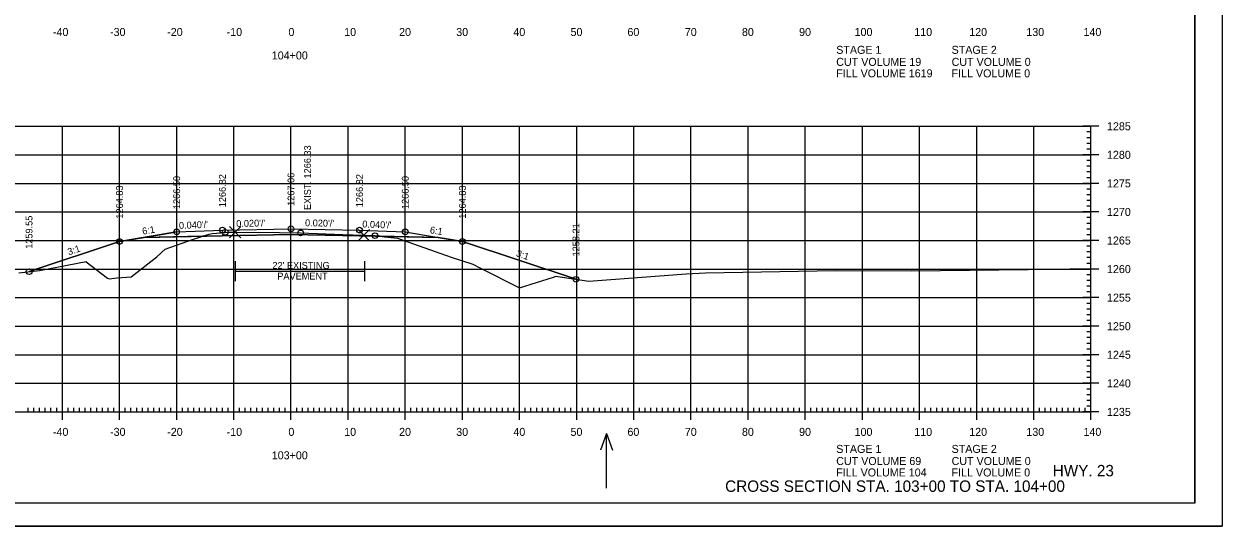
# Model space of a CAD drawing. Extents: x 1406028 to 1412453, y 321733 to 325986.
# Drawn here: x 1406543.2 to 1406752.8, y 322146 to 322233.9 of the extents above; entities that cross this region are included whole.
import ezdxf

# ---------------------------------------------------------------- set-up
doc = ezdxf.new("R2010")
doc.units = 0
for name, color, linetype in [('R_Alt Surface', 7, 'Continuous'), ('R_Axis', 7, 'Continuous'), ('R_Axis Annot', 7, 'Continuous'), ('R_Border', 7, 'Continuous'), ('R_Draft', 7, 'Continuous'), ('R_Exist Surface', 7, 'Continuous'), ('R_Fin Surface', 7, 'Continuous'), ('R_Fin Surface Annot', 7, 'Continuous'), ('R_Grid', 7, 'Continuous'), ('R_No Plot', 7, 'Continuous'), ('R_Proposed Const Limits', 7, 'Continuous'), ('R_Proposed Road', 7, 'Continuous'), ('R_Water Annot', 7, 'Continuous'), ('R_Xsect Elev', 7, 'Continuous')]:
    doc.layers.add(name, color=color, linetype=linetype)

msp = doc.modelspace()

# ---------------------------------------------------------------- linework, layer by layer
at = {"layer": 'R_Alt Surface'}
msp.add_lwpolyline([(1406564.16, 322196.54), (1406577.88, 322196.81), (1406589.88, 322197.05), (1406601.88, 322196.81), (1406615.61, 322196.54)], dxfattribs=at)
at = {"layer": 'R_Axis'}
for p, q in [((1406731.28, 322215.99), (1406728.48, 322215.99)), ((1406729.88, 322214.99), (1406729.18, 322214.99)), ((1406729.88, 322165.99), (1406729.88, 322215.99)), ((1406729.88, 322213.99), (1406729.18, 322213.99)), ((1406729.88, 322212.99), (1406729.18, 322212.99)), ((1406731.28, 322210.99), (1406728.48, 322210.99)), ((1406729.88, 322211.99), (1406729.18, 322211.99)), ((1406729.88, 322209.99), (1406729.18, 322209.99)), ((1406729.88, 322208.99), (1406729.18, 322208.99)), ((1406729.88, 322207.99), (1406729.18, 322207.99)), ((1406729.88, 322206.99), (1406729.18, 322206.99)), ((1406731.28, 322205.99), (1406728.48, 322205.99)), ((1406729.88, 322204.99), (1406729.18, 322204.99)), ((1406729.88, 322203.99), (1406729.18, 322203.99)), ((1406729.88, 322202.99), (1406729.18, 322202.99)), ((1406731.28, 322200.99), (1406728.48, 322200.99)), ((1406729.88, 322201.99), (1406729.18, 322201.99)), ((1406729.88, 322199.99), (1406729.18, 322199.99)), ((1406729.88, 322198.99), (1406729.18, 322198.99)), ((1406729.88, 322197.99), (1406729.18, 322197.99)), ((1406731.28, 322195.99), (1406728.48, 322195.99)), ((1406729.88, 322196.99), (1406729.18, 322196.99)), ((1406729.88, 322194.99), (1406729.18, 322194.99)), ((1406729.88, 322193.99), (1406729.18, 322193.99)), ((1406729.88, 322192.99), (1406729.18, 322192.99)), ((1406729.88, 322191.99), (1406729.18, 322191.99)), ((1406731.28, 322190.99), (1406728.48, 322190.99)), ((1406729.88, 322189.99), (1406729.18, 322189.99)), ((1406729.88, 322188.99), (1406729.18, 322188.99)), ((1406729.88, 322187.99), (1406729.18, 322187.99)), ((1406731.28, 322185.99), (1406728.48, 322185.99)), ((1406729.88, 322186.99), (1406729.18, 322186.99)), ((1406729.88, 322184.99), (1406729.18, 322184.99)), ((1406729.88, 322183.99), (1406729.18, 322183.99)), ((1406729.88, 322182.99), (1406729.18, 322182.99)), ((1406729.88, 322181.99), (1406729.18, 322181.99)), ((1406731.28, 322180.99), (1406728.48, 322180.99)), ((1406729.88, 322179.99), (1406729.18, 322179.99)), ((1406729.88, 322178.99), (1406729.18, 322178.99)), ((1406729.88, 322177.99), (1406729.18, 322177.99)), ((1406729.88, 322176.99), (1406729.18, 322176.99)), ((1406731.28, 322175.99), (1406728.48, 322175.99)), ((1406729.88, 322174.99), (1406729.18, 322174.99)), ((1406729.88, 322173.99), (1406729.18, 322173.99)), ((1406729.88, 322172.99), (1406729.18, 322172.99)), ((1406731.28, 322170.99), (1406728.48, 322170.99)), ((1406729.88, 322171.99), (1406729.18, 322171.99)), ((1406729.88, 322169.99), (1406729.18, 322169.99)), ((1406729.88, 322168.99), (1406729.18, 322168.99)), ((1406543.88, 322165.99), (1406543.88, 322166.69)), ((1406544.88, 322165.99), (1406544.88, 322166.69)), ((1406545.88, 322165.99), (1406545.88, 322166.69)), ((1406546.88, 322165.99), (1406546.88, 322166.69)), ((1406547.88, 322165.99), (1406547.88, 322166.69)), ((1406548.88, 322165.99), (1406548.88, 322166.69)), ((1406549.88, 322164.59), (1406549.88, 322167.39)), ((1406550.88, 322165.99), (1406550.88, 322166.69)), ((1406551.88, 322165.99), (1406551.88, 322166.69)), ((1406552.88, 322165.99), (1406552.88, 322166.69)), ((1406553.88, 322165.99), (1406553.88, 322166.69)), ((1406554.88, 322165.99), (1406554.88, 322166.69)), ((1406555.88, 322165.99), (1406555.88, 322166.69)), ((1406556.88, 322165.99), (1406556.88, 322166.69)), ((1406557.88, 322165.99), (1406557.88, 322166.69)), ((1406558.88, 322165.99), (1406558.88, 322166.69)), ((1406559.88, 322164.59), (1406559.88, 322167.39)), ((1406560.88, 322165.99), (1406560.88, 322166.69)), ((1406561.88, 322165.99), (1406561.88, 322166.69)), ((1406562.88, 322165.99), (1406562.88, 322166.69)), ((1406563.88, 322165.99), (1406563.88, 322166.69)), ((1406564.88, 322165.99), (1406564.88, 322166.69)), ((1406565.88, 322165.99), (1406565.88, 322166.69)), ((1406566.88, 322165.99), (1406566.88, 322166.69)), ((1406567.88, 322165.99), (1406567.88, 322166.69)), ((1406568.88, 322165.99), (1406568.88, 322166.69)), ((1406569.88, 322164.59), (1406569.88, 322167.39)), ((1406570.88, 322165.99), (1406570.88, 322166.69)), ((1406571.88, 322165.99), (1406571.88, 322166.69)), ((1406572.88, 322165.99), (1406572.88, 322166.69)), ((1406573.88, 322165.99), (1406573.88, 322166.69)), ((1406574.88, 322165.99), (1406574.88, 322166.69)), ((1406575.88, 322165.99), (1406575.88, 322166.69)), ((1406576.88, 322165.99), (1406576.88, 322166.69)), ((1406577.88, 322165.99), (1406577.88, 322166.69)), ((1406578.88, 322165.99), (1406578.88, 322166.69)), ((1406579.88, 322164.59), (1406579.88, 322167.39)), ((1406580.88, 322165.99), (1406580.88, 322166.69)), ((1406581.88, 322165.99), (1406581.88, 322166.69)), ((1406582.88, 322165.99), (1406582.88, 322166.69)), ((1406583.88, 322165.99), (1406583.88, 322166.69)), ((1406584.88, 322165.99), (1406584.88, 322166.69)), ((1406585.88, 322165.99), (1406585.88, 322166.69)), ((1406586.88, 322165.99), (1406586.88, 322166.69)), ((1406587.88, 322165.99), (1406587.88, 322166.69)), ((1406588.88, 322165.99), (1406588.88, 322166.69)), ((1406589.88, 322164.59), (1406589.88, 322167.39)), ((1406590.88, 322165.99), (1406590.88, 322166.69)), ((1406591.88, 322165.99), (1406591.88, 322166.69)), ((1406592.88, 322165.99), (1406592.88, 322166.69)), ((1406593.88, 322165.99), (1406593.88, 322166.69)), ((1406594.88, 322165.99), (1406594.88, 322166.69)), ((1406595.88, 322165.99), (1406595.88, 322166.69)), ((1406596.88, 322165.99), (1406596.88, 322166.69)), ((1406597.88, 322165.99), (1406597.88, 322166.69)), ((1406598.88, 322165.99), (1406598.88, 322166.69)), ((1406599.88, 322164.59), (1406599.88, 322167.39)), ((1406600.88, 322165.99), (1406600.88, 322166.69)), ((1406601.88, 322165.99), (1406601.88, 322166.69)), ((1406602.88, 322165.99), (1406602.88, 322166.69)), ((1406603.88, 322165.99), (1406603.88, 322166.69)), ((1406604.88, 322165.99), (1406604.88, 322166.69)), ((1406605.88, 322165.99), (1406605.88, 322166.69)), ((1406606.88, 322165.99), (1406606.88, 322166.69)), ((1406607.88, 322165.99), (1406607.88, 322166.69)), ((1406608.88, 322165.99), (1406608.88, 322166.69)), ((1406609.88, 322164.59), (1406609.88, 322167.39)), ((1406610.88, 322165.99), (1406610.88, 322166.69)), ((1406611.88, 322165.99), (1406611.88, 322166.69)), ((1406612.88, 322165.99), (1406612.88, 322166.69)), ((1406613.88, 322165.99), (1406613.88, 322166.69)), ((1406614.88, 322165.99), (1406614.88, 322166.69)), ((1406615.88, 322165.99), (1406615.88, 322166.69)), ((1406616.88, 322165.99), (1406616.88, 322166.69)), ((1406617.88, 322165.99), (1406617.88, 322166.69)), ((1406618.88, 322165.99), (1406618.88, 322166.69)), ((1406619.88, 322164.59), (1406619.88, 322167.39)), ((1406620.88, 322165.99), (1406620.88, 322166.69)), ((1406621.88, 322165.99), (1406621.88, 322166.69)), ((1406622.88, 322165.99), (1406622.88, 322166.69)), ((1406623.88, 322165.99), (1406623.88, 322166.69)), ((1406624.88, 322165.99), (1406624.88, 322166.69)), ((1406625.88, 322165.99), (1406625.88, 322166.69)), ((1406626.88, 322165.99), (1406626.88, 322166.69)), ((1406627.88, 322165.99), (1406627.88, 322166.69)), ((1406628.88, 322165.99), (1406628.88, 322166.69)), ((1406629.88, 322164.59), (1406629.88, 322167.39)), ((1406630.88, 322165.99), (1406630.88, 322166.69)), ((1406631.88, 322165.99), (1406631.88, 322166.69)), ((1406632.88, 322165.99), (1406632.88, 322166.69)), ((1406633.88, 322165.99), (1406633.88, 322166.69)), ((1406634.88, 322165.99), (1406634.88, 322166.69)), ((1406635.88, 322165.99), (1406635.88, 322166.69)), ((1406636.88, 322165.99), (1406636.88, 322166.69)), ((1406637.88, 322165.99), (1406637.88, 322166.69)), ((1406638.88, 322165.99), (1406638.88, 322166.69)), ((1406639.88, 322164.59), (1406639.88, 322167.39)), ((1406640.88, 322165.99), (1406640.88, 322166.69)), ((1406641.88, 322165.99), (1406641.88, 322166.69)), ((1406642.88, 322165.99), (1406642.88, 322166.69)), ((1406643.88, 322165.99), (1406643.88, 322166.69)), ((1406644.88, 322165.99), (1406644.88, 322166.69)), ((1406645.88, 322165.99), (1406645.88, 322166.69)), ((1406646.88, 322165.99), (1406646.88, 322166.69)), ((1406647.88, 322165.99), (1406647.88, 322166.69)), ((1406648.88, 322165.99), (1406648.88, 322166.69)), ((1406649.88, 322164.59), (1406649.88, 322167.39)), ((1406650.88, 322165.99), (1406650.88, 322166.69)), ((1406651.88, 322165.99), (1406651.88, 322166.69)), ((1406652.88, 322165.99), (1406652.88, 322166.69)), ((1406653.88, 322165.99), (1406653.88, 322166.69)), ((1406654.88, 322165.99), (1406654.88, 322166.69)), ((1406655.88, 322165.99), (1406655.88, 322166.69)), ((1406656.88, 322165.99), (1406656.88, 322166.69)), ((1406657.88, 322165.99), (1406657.88, 322166.69)), ((1406658.88, 322165.99), (1406658.88, 322166.69)), ((1406659.88, 322164.59), (1406659.88, 322167.39)), ((1406660.88, 322165.99), (1406660.88, 322166.69)), ((1406661.88, 322165.99), (1406661.88, 322166.69)), ((1406662.88, 322165.99), (1406662.88, 322166.69)), ((1406663.88, 322165.99), (1406663.88, 322166.69)), ((1406664.88, 322165.99), (1406664.88, 322166.69)), ((1406665.88, 322165.99), (1406665.88, 322166.69)), ((1406666.88, 322165.99), (1406666.88, 322166.69)), ((1406667.88, 322165.99), (1406667.88, 322166.69)), ((1406668.88, 322165.99), (1406668.88, 322166.69)), ((1406669.88, 322164.59), (1406669.88, 322167.39)), ((1406670.88, 322165.99), (1406670.88, 322166.69)), ((1406671.88, 322165.99), (1406671.88, 322166.69)), ((1406672.88, 322165.99), (1406672.88, 322166.69)), ((1406673.88, 322165.99), (1406673.88, 322166.69)), ((1406674.88, 322165.99), (1406674.88, 322166.69)), ((1406675.88, 322165.99), (1406675.88, 322166.69)), ((1406676.88, 322165.99), (1406676.88, 322166.69)), ((1406677.88, 322165.99), (1406677.88, 322166.69)), ((1406678.88, 322165.99), (1406678.88, 322166.69)), ((1406679.88, 322164.59), (1406679.88, 322167.39)), ((1406680.88, 322165.99), (1406680.88, 322166.69)), ((1406681.88, 322165.99), (1406681.88, 322166.69)), ((1406682.88, 322165.99), (1406682.88, 322166.69)), ((1406683.88, 322165.99), (1406683.88, 322166.69)), ((1406684.88, 322165.99), (1406684.88, 322166.69)), ((1406685.88, 322165.99), (1406685.88, 322166.69)), ((1406686.88, 322165.99), (1406686.88, 322166.69)), ((1406687.88, 322165.99), (1406687.88, 322166.69)), ((1406688.88, 322165.99), (1406688.88, 322166.69)), ((1406689.88, 322164.59), (1406689.88, 322167.39)), ((1406690.88, 322165.99), (1406690.88, 322166.69)), ((1406691.88, 322165.99), (1406691.88, 322166.69)), ((1406692.88, 322165.99), (1406692.88, 322166.69)), ((1406693.88, 322165.99), (1406693.88, 322166.69)), ((1406694.88, 322165.99), (1406694.88, 322166.69)), ((1406695.88, 322165.99), (1406695.88, 322166.69)), ((1406696.88, 322165.99), (1406696.88, 322166.69)), ((1406697.88, 322165.99), (1406697.88, 322166.69)), ((1406698.88, 322165.99), (1406698.88, 322166.69)), ((1406699.88, 322164.59), (1406699.88, 322167.39)), ((1406700.88, 322165.99), (1406700.88, 322166.69)), ((1406701.88, 322165.99), (1406701.88, 322166.69)), ((1406702.88, 322165.99), (1406702.88, 322166.69)), ((1406703.88, 322165.99), (1406703.88, 322166.69)), ((1406704.88, 322165.99), (1406704.88, 322166.69)), ((1406705.88, 322165.99), (1406705.88, 322166.69)), ((1406706.88, 322165.99), (1406706.88, 322166.69)), ((1406707.88, 322165.99), (1406707.88, 322166.69)), ((1406708.88, 322165.99), (1406708.88, 322166.69)), ((1406709.88, 322164.59), (1406709.88, 322167.39)), ((1406710.88, 322165.99), (1406710.88, 322166.69)), ((1406711.88, 322165.99), (1406711.88, 322166.69)), ((1406712.88, 322165.99), (1406712.88, 322166.69)), ((1406713.88, 322165.99), (1406713.88, 322166.69)), ((1406714.88, 322165.99), (1406714.88, 322166.69)), ((1406715.88, 322165.99), (1406715.88, 322166.69)), ((1406716.88, 322165.99), (1406716.88, 322166.69)), ((1406717.88, 322165.99), (1406717.88, 322166.69)), ((1406718.88, 322165.99), (1406718.88, 322166.69)), ((1406719.88, 322164.59), (1406719.88, 322167.39)), ((1406720.88, 322165.99), (1406720.88, 322166.69)), ((1406721.88, 322165.99), (1406721.88, 322166.69)), ((1406722.88, 322165.99), (1406722.88, 322166.69)), ((1406723.88, 322165.99), (1406723.88, 322166.69)), ((1406724.88, 322165.99), (1406724.88, 322166.69)), ((1406725.88, 322165.99), (1406725.88, 322166.69)), ((1406726.88, 322165.99), (1406726.88, 322166.69)), ((1406727.88, 322165.99), (1406727.88, 322166.69)), ((1406728.88, 322165.99), (1406728.88, 322166.69)), ((1406729.88, 322167.99), (1406729.18, 322167.99)), ((1406729.88, 322166.99), (1406729.18, 322166.99)), ((1406729.88, 322164.59), (1406729.88, 322167.39)), ((1406449.88, 322165.99), (1406729.88, 322165.99)), ((1406731.28, 322165.99), (1406728.48, 322165.99))]:
    msp.add_line(p, q, dxfattribs=at)
at = {"layer": 'R_Border'}
for q in [(1406748.06, 322355.45), (1406431.88, 322149.99)]:
    msp.add_line((1406748.06, 322149.99), q, dxfattribs=at)
at = {"layer": 'R_Draft'}
for p, q in [((1406580.11, 322192.36), (1406580.11, 322188.87)), ((1406602.74, 322192.36), (1406602.74, 322188.87)), ((1406580.13, 322190.65), (1406602.72, 322190.65))]:
    msp.add_line(p, q, dxfattribs=at)
at = {"layer": 'R_Exist Surface'}
msp.add_lwpolyline([(1406542.27, 322190.36), (1406545.85, 322190.73), (1406554.02, 322192.3), (1406554.02, 322192.28), (1406557.75, 322189.41), (1406558.04, 322189.31), (1406559.44, 322189.44), (1406561.91, 322189.65), (1406566.41, 322193.16), (1406567.87, 322194.5), (1406572.64, 322196.15), (1406575.57, 322197.12), (1406576.1, 322197.19), (1406578.36, 322197.42), (1406578.94, 322197.43), (1406580.11, 322197.47), (1406587.88, 322197.38), (1406591.57, 322197.32), (1406598.94, 322197.06), (1406602.61, 322196.92), (1406603.3, 322196.89), (1406604.58, 322196.84), (1406606.27, 322196.64), (1406608.54, 322196.4), (1406617.9, 322193.07), (1406621.73, 322191.86), (1406623.07, 322191.15), (1406629.85, 322187.68), (1406635.84, 322189.59), (1406636.28, 322189.76), (1406636.58, 322189.69), (1406642.03, 322188.85), (1406659.01, 322190.13), (1406662.42, 322190.35), (1406685.24, 322190.72), (1406698.43, 322190.69), (1406718.91, 322190.89), (1406729.88, 322191.07)], dxfattribs=at)
at = {"layer": 'R_Fin Surface'}
for points in [[(1406544.04, 322190.54), (1406559.88, 322195.82), (1406564.16, 322196.54), (1406569.88, 322197.49), (1406577.88, 322197.81), (1406589.88, 322198.05), (1406601.88, 322197.81), (1406609.88, 322197.49), (1406615.61, 322196.54), (1406619.88, 322195.82), (1406639.76, 322189.2)], [(1406569.88, 322197.49), (1406577.88, 322197.81), (1406589.88, 322198.05), (1406601.88, 322197.81), (1406609.88, 322197.49)]]:
    msp.add_lwpolyline(points, dxfattribs=at)
at = {"layer": 'R_Grid'}
for p, q in [((1406449.88, 322215.99), (1406729.88, 322215.99)), ((1406549.88, 322165.99), (1406549.88, 322215.99)), ((1406559.88, 322165.99), (1406559.88, 322215.99)), ((1406569.88, 322165.99), (1406569.88, 322215.99)), ((1406579.88, 322165.99), (1406579.88, 322215.99)), ((1406589.88, 322165.99), (1406589.88, 322215.99)), ((1406599.88, 322165.99), (1406599.88, 322215.99)), ((1406609.88, 322165.99), (1406609.88, 322215.99)), ((1406619.88, 322165.99), (1406619.88, 322215.99)), ((1406629.88, 322165.99), (1406629.88, 322215.99)), ((1406639.88, 322165.99), (1406639.88, 322215.99)), ((1406649.88, 322165.99), (1406649.88, 322215.99)), ((1406659.88, 322165.99), (1406659.88, 322215.99)), ((1406669.88, 322165.99), (1406669.88, 322215.99)), ((1406679.88, 322165.99), (1406679.88, 322215.99)), ((1406689.88, 322165.99), (1406689.88, 322215.99)), ((1406699.88, 322165.99), (1406699.88, 322215.99)), ((1406709.88, 322165.99), (1406709.88, 322215.99)), ((1406719.88, 322165.99), (1406719.88, 322215.99)), ((1406729.88, 322165.99), (1406729.88, 322215.99)), ((1406449.88, 322210.99), (1406729.88, 322210.99)), ((1406449.88, 322205.99), (1406729.88, 322205.99)), ((1406449.88, 322200.99), (1406729.88, 322200.99)), ((1406449.88, 322195.99), (1406729.88, 322195.99)), ((1406449.88, 322190.99), (1406729.88, 322190.99)), ((1406449.88, 322185.99), (1406729.88, 322185.99)), ((1406449.88, 322180.99), (1406729.88, 322180.99)), ((1406449.88, 322175.99), (1406729.88, 322175.99)), ((1406449.88, 322170.99), (1406729.88, 322170.99)), ((1406449.88, 322165.99), (1406729.88, 322165.99))]:
    msp.add_line(p, q, dxfattribs=at)
at = {"layer": 'R_No Plot'}
msp.add_line((1406419.48, 322146.01), (1406752.82, 322146.01), dxfattribs=at)
for points in [[(1406419.48, 322359.34), (1406752.82, 322359.34), (1406752.82, 322146.01), (1406419.48, 322146.01)], [(1406665.8, 322355.45), (1406685.42, 322355.45), (1406685.42, 322345.57), (1406701.54, 322345.57), (1406724.73, 322345.57), (1406724.73, 322321.24), (1406748.06, 322321.24), (1406748.06, 322149.99), (1406431.88, 322149.99), (1406431.88, 322355.45)], [(1406544.04, 322190.54), (1406545.85, 322190.73), (1406554.02, 322192.3), (1406554.02, 322192.28), (1406557.75, 322189.41), (1406558.04, 322189.31), (1406559.44, 322189.44), (1406561.91, 322189.65), (1406566.41, 322193.16), (1406567.87, 322194.5), (1406572.64, 322196.15), (1406574.42, 322196.74), (1406564.16, 322196.54), (1406559.88, 322195.82)], [(1406574.42, 322196.74), (1406575.57, 322197.12), (1406576.1, 322197.19), (1406578.36, 322197.42), (1406578.94, 322197.43), (1406580.11, 322197.47), (1406587.88, 322197.38), (1406591.57, 322197.32), (1406598.94, 322197.06), (1406602.61, 322196.92), (1406603.3, 322196.89), (1406604.58, 322196.84), (1406605.44, 322196.74), (1406601.88, 322196.81), (1406589.88, 322197.05), (1406577.88, 322196.81)], [(1406605.44, 322196.74), (1406606.27, 322196.64), (1406608.54, 322196.4), (1406617.9, 322193.07), (1406621.73, 322191.86), (1406623.07, 322191.15), (1406629.85, 322187.68), (1406635.84, 322189.59), (1406636.28, 322189.76), (1406636.58, 322189.69), (1406639.76, 322189.2), (1406619.88, 322195.82), (1406617.43, 322196.23), (1406617.42, 322196.23), (1406615.61, 322196.54)]]:
    msp.add_lwpolyline(points, close=True, dxfattribs=at)
for points in [[(1406580.11, 322197.47), (1406579.11, 322198.47), (1406580.11, 322197.47), (1406579.11, 322196.47), (1406580.11, 322197.47), (1406581.11, 322196.47), (1406580.11, 322197.47), (1406581.11, 322198.47)], [(1406602.61, 322196.92), (1406601.61, 322197.92), (1406602.61, 322196.92), (1406601.61, 322195.92), (1406602.61, 322196.92), (1406603.61, 322195.92), (1406602.61, 322196.92), (1406603.61, 322197.92)]]:
    msp.add_lwpolyline(points, dxfattribs=at)
for centre in [(1406569.88, 322197.49), (1406577.88, 322197.81), (1406578.36, 322197.42), (1406589.88, 322198.05), (1406591.57, 322197.32), (1406601.88, 322197.81), (1406609.88, 322197.49), (1406559.88, 322195.82), (1406604.58, 322196.84), (1406619.88, 322195.82), (1406544.04, 322190.54), (1406639.76, 322189.2)]:
    msp.add_circle(centre, 0.5, dxfattribs=at)
at = {"layer": 'R_Proposed Const Limits'}
for points in [[(1406559.88, 322195.82), (1406544.04, 322190.54)], [(1406619.88, 322195.82), (1406639.76, 322189.2)]]:
    msp.add_lwpolyline(points, dxfattribs=at)
at = {"layer": 'R_Proposed Road'}
for points in [[(1406569.88, 322197.49), (1406559.88, 322195.82)], [(1406609.88, 322197.49), (1406619.88, 322195.82)]]:
    msp.add_lwpolyline(points, dxfattribs=at)
at = {"layer": 'R_Water Annot'}
for p, q in [((1406645.1, 322162.22), (1406644.03, 322159.29)), ((1406645.1, 322152.65), (1406645.1, 322162.22)), ((1406645.1, 322162.22), (1406646.17, 322159.29))]:
    msp.add_line(p, q, dxfattribs=at)

# ---------------------------------------------------------------- texts
at = {"layer": 'R_Axis Annot'}
for s, p in [('-40', (1406548.22, 322231.79)), ('-30', (1406558.22, 322231.79)), ('-20', (1406568.22, 322231.79)), ('-10', (1406578.62, 322231.79)), ('0', (1406589.43, 322231.79)), ('10', (1406599.19, 322231.79)), ('20', (1406608.8, 322231.79)), ('30', (1406618.8, 322231.79)), ('40', (1406628.8, 322231.79)), ('50', (1406638.8, 322231.79)), ('60', (1406648.76, 322231.79)), ('70', (1406658.8, 322231.79)), ('80', (1406668.8, 322231.79)), ('90', (1406678.8, 322231.79)), ('100', (1406688.51, 322231.79)), ('110', (1406698.96, 322231.79)), ('120', (1406708.57, 322231.79)), ('130', (1406718.57, 322231.79)), ('140', (1406728.57, 322231.79)), ('STAGE 1', (1406685.3, 322228.67)), ('STAGE 2', (1406705.49, 322228.67)), ('104+00', (1406586.52, 322227.69)), ('CUT VOLUME 19', (1406685.3, 322226.56)), ('CUT VOLUME 0', (1406705.49, 322226.56)), ('FILL VOLUME 1619', (1406685.3, 322224.56)), ('FILL VOLUME 0', (1406705.49, 322224.56)), ('1285', (1406732.68, 322215.29)), ('1280', (1406732.68, 322210.29)), ('1275', (1406732.68, 322205.29)), ('1270', (1406732.68, 322200.29)), ('1265', (1406732.68, 322195.29)), ('1260', (1406732.68, 322190.29)), ('1255', (1406732.68, 322185.29)), ('1250', (1406732.68, 322180.29)), ('1245', (1406732.68, 322175.29)), ('1240', (1406732.68, 322170.29)), ('1235', (1406732.68, 322165.29)), ('-40', (1406548.22, 322161.79)), ('-30', (1406558.22, 322161.79)), ('-20', (1406568.22, 322161.79)), ('-10', (1406578.62, 322161.79)), ('0', (1406589.43, 322161.79)), ('10', (1406599.19, 322161.79)), ('20', (1406608.8, 322161.79)), ('30', (1406618.8, 322161.79)), ('40', (1406628.8, 322161.79)), ('50', (1406638.8, 322161.79)), ('60', (1406648.76, 322161.79)), ('70', (1406658.8, 322161.79)), ('80', (1406668.8, 322161.79)), ('90', (1406678.8, 322161.79)), ('100', (1406688.51, 322161.79)), ('110', (1406698.96, 322161.79)), ('120', (1406708.57, 322161.79)), ('130', (1406718.57, 322161.79)), ('140', (1406728.57, 322161.79)), ('STAGE 1', (1406685.3, 322158.81)), ('STAGE 2', (1406705.49, 322158.81)), ('103+00', (1406586.52, 322157.69)), ('CUT VOLUME 69', (1406685.3, 322156.69)), ('CUT VOLUME 0', (1406705.49, 322156.69)), ('FILL VOLUME 104', (1406685.3, 322154.69)), ('FILL VOLUME 0', (1406705.49, 322154.69))]:
    msp.add_text(s, height=1.4, dxfattribs=at).set_placement(p)
at = {"layer": 'R_Draft'}
for s, height, p in [("22' EXISTING ", 1.2, (1406586.63, 322191.03)), ('PAVEMENT', 1.2, (1406587.48, 322189.16)), ('HWY. 23', 2, (1406723.19, 322154.71)), ('CROSS SECTION STA. 103+00 TO STA. 104+00', 2, (1406665.86, 322151.99))]:
    msp.add_text(s, height=height, dxfattribs=at).set_placement(p)
at = {"layer": 'R_Fin Surface Annot'}
for s, rotation, p in [('1266.50', 90, (1406570.48, 322201.49)), ('1266.82', 90, (1406578.48, 322201.81)), ('1267.06', 90, (1406590.48, 322202.05)), ('1266.82', 90, (1406602.48, 322201.81)), ('1266.50', 90, (1406610.48, 322201.49)), ('1264.83', 90, (1406560.48, 322199.82)), ('1264.83', 90, (1406620.48, 322199.82)), ('1259.55', 90, (1406544.64, 322194.54)), ('6:1', 9.4642, (1406563.95, 322197.01)), ("0.040'/'", 2.2906, (1406570.3, 322198.01)), ("0.020'/'", 1.1458, (1406580.31, 322198.36)), ("0.020'/'", 358.8542, (1406592.33, 322198.5)), ("0.040'/'", 357.7094, (1406602.34, 322198.29)), ('6:1', 350.5358, (1406614.12, 322197.29)), ('1258.21', 90, (1406640.36, 322193.2)), ('3:1', 18.4332, (1406551.01, 322193.39)), ('3:1', 341.5668, (1406629.19, 322193.25))]:
    msp.add_text(s, height=1.2, rotation=rotation, dxfattribs=at).set_placement(p)
at = {"layer": 'R_No Plot'}
for p in [(1406575.52, 322197.07), (1406608.5, 322196.35), (1406567.83, 322194.45), (1406553.98, 322192.25), (1406621.68, 322191.81), (1406561.86, 322189.6), (1406636.24, 322189.71), (1406662.38, 322190.3), (1406698.39, 322190.64), (1406558, 322189.26), (1406629.8, 322187.63), (1406641.99, 322188.8)]:
    msp.add_text('+', height=0.1, dxfattribs=at).set_placement(p)
at = {"layer": 'R_Xsect Elev'}
msp.add_text('EXIST. 1266.33', height=1.2, rotation=90, dxfattribs=at).set_placement((1406593.37, 322201.32))

doc.saveas('drawing.dxf')
